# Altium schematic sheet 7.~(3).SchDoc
size 420 x 297 mm
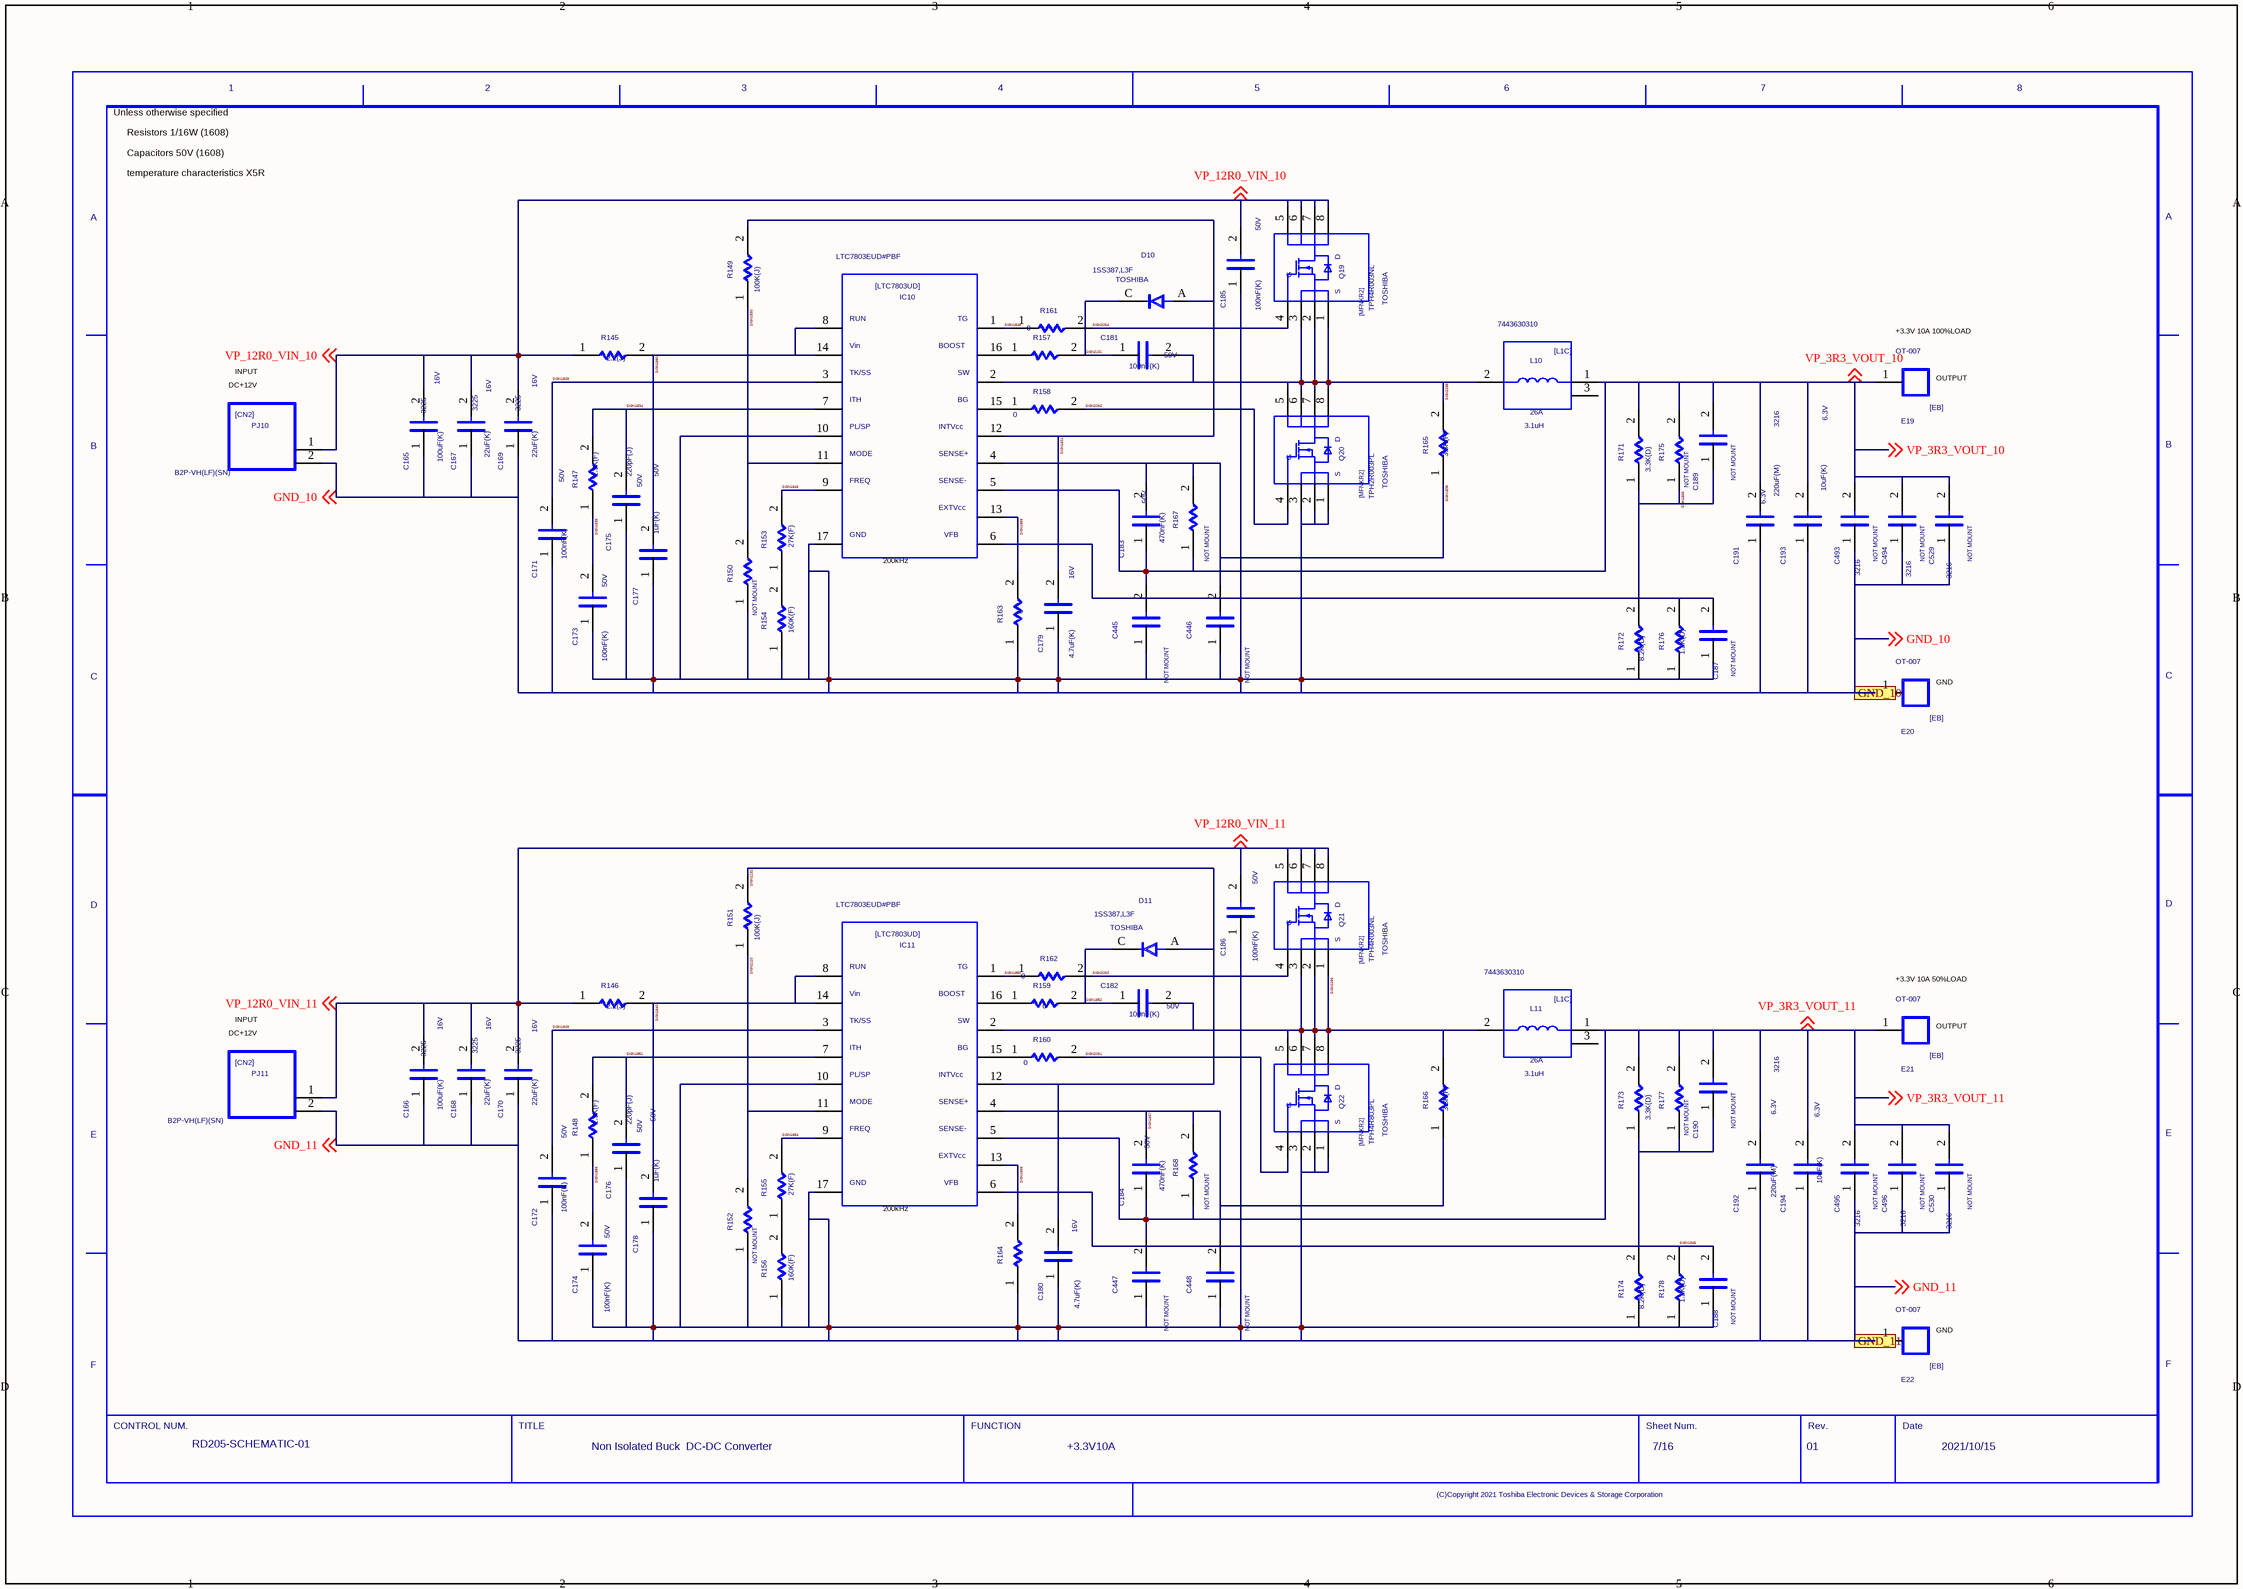
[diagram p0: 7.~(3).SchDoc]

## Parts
C165  SIZECODESMD: 3225  VAL2: 16V  VAL1: 100uF(K)  (hidden comment: C)
C166  SIZECODESMD: 3225  VAL2: 16V  VAL1: 100uF(K)  (hidden comment: C)
C167  SIZECODESMD: 3225  VAL2: 16V  VAL1: 22uF(K)  (hidden comment: C)
C168  SIZECODESMD: 3225  VAL2: 16V  VAL1: 22uF(K)  (hidden comment: C)
C169  SIZECODESMD: 3225  VAL2: 16V  VAL1: 22uF(K)  (hidden comment: C)
C170  SIZECODESMD: 3225  VAL2: 16V  VAL1: 22uF(K)  (hidden comment: C)
C171  VAL2: 50V  VAL1: 100nF(K)  (hidden comment: C)
C172  VAL2: 50V  VAL1: 100nF(K)  (hidden comment: C)
C173  VAL2: 50V  VAL1: 100nF(K)  (hidden comment: C)
C174  VAL2: 50V  VAL1: 100nF(K)  (hidden comment: C)
C175  VAL2: 50V  VAL1: 220pF(J)  (hidden comment: C)
C176  VAL2: 50V  VAL1: 220pF(J)  (hidden comment: C)
C177  VAL2: 50V  VAL1: 1uF(K)  (hidden comment: C)
C178  VAL2: 50V  VAL1: 1uF(K)  (hidden comment: C)
C179  VAL2: 16V  VAL1: 4.7uF(K)  (hidden comment: C)
C180  VAL2: 16V  VAL1: 4.7uF(K)  (hidden comment: C)
C181  VAL2: 50V  VAL1: 100nF(K)  (hidden comment: C)
C182  VAL2: 50V  VAL1: 100nF(K)  (hidden comment: C)
C183  VAL2: 50V  VAL1: 470nF(K)  (hidden comment: C)
C184  VAL2: 50V  VAL1: 470nF(K)  (hidden comment: C)
C185  VAL2: 50V  VAL1: 100nF(K)  (hidden comment: C)
C186  VAL2: 50V  VAL1: 100nF(K)  (hidden comment: C)
C187  NOTMOUNT: NOT MOUNT  (hidden comment: C)
C188  NOTMOUNT: NOT MOUNT  (hidden comment: C)
C189  NOTMOUNT: NOT MOUNT  (hidden comment: C)
C190  NOTMOUNT: NOT MOUNT  (hidden comment: C)
C191  SIZECODESMD: 3216  VAL2: 6.3V  VAL1: 220uF(M)  (hidden comment: C)
C192  SIZECODESMD: 3216  VAL2: 6.3V  VAL1: 220uF(M)  (hidden comment: C)
C193  VAL2: 6.3V  VAL1: 10uF(K)  (hidden comment: C)
C194  VAL2: 6.3V  VAL1: 10uF(K)  (hidden comment: C)
C445  NOTMOUNT: NOT MOUNT  (hidden comment: C)
C446  NOTMOUNT: NOT MOUNT  (hidden comment: C)
C447  NOTMOUNT: NOT MOUNT  (hidden comment: C)
C448  NOTMOUNT: NOT MOUNT  (hidden comment: C)
C493  NOTMOUNT: NOT MOUNT  SIZECODESMD: 3216  (hidden comment: C)
C494  NOTMOUNT: NOT MOUNT  SIZECODESMD: 3216  (hidden comment: C)
C495  NOTMOUNT: NOT MOUNT  SIZECODESMD: 3216  (hidden comment: C)
C496  NOTMOUNT: NOT MOUNT  SIZECODESMD: 3216  (hidden comment: C)
C529  NOTMOUNT: NOT MOUNT  SIZECODESMD: 3216  (hidden comment: C)
C530  NOTMOUNT: NOT MOUNT  SIZECODESMD: 3216  (hidden comment: C)
D10  USERCOMPTEXT3: TOSHIBA  VAL3: 1SS387,L3F  (hidden comment: D)
D11  USERCOMPTEXT3: TOSHIBA  VAL3: 1SS387,L3F  (hidden comment: D)
E19  VAL3: OT-007  (hidden comment: EB)
E20  VAL3: OT-007  (hidden comment: EB)
E21  VAL3: OT-007  (hidden comment: EB)
E22  VAL3: OT-007  (hidden comment: EB)
IC10  VAL3: LTC7803EUD#PBF  (hidden comment: LTC7803UD)
IC11  VAL3: LTC7803EUD#PBF  (hidden comment: LTC7803UD)
L10  VAL3: 7443630310  VAL2: 26A  VAL1: 3.1uH  (hidden comment: L1C)
L11  VAL3: 7443630310  VAL2: 26A  VAL1: 3.1uH  (hidden comment: L1C)
PJ10  VAL3: B2P-VH(LF)(SN)  (hidden comment: CN2)
PJ11  VAL3: B2P-VH(LF)(SN)  (hidden comment: CN2)
Q19  USERCOMPTEXT3: TOSHIBA  VAL3: TPH4R003NL  (hidden comment: MFNKR2)
Q20  USERCOMPTEXT3: TOSHIBA  VAL3: TPH2R003PL  (hidden comment: MFNKR2)
Q21  USERCOMPTEXT3: TOSHIBA  VAL3: TPH4R003NL  (hidden comment: MFNKR2)
Q22  USERCOMPTEXT3: TOSHIBA  VAL3: TPH4R803PL  (hidden comment: MFNKR2)
R145  VAL1: 2.2(J)  (hidden comment: R)
R146  VAL1: 2.2(J)  (hidden comment: R)
R147  VAL1: 1.3K(F)  (hidden comment: R)
R148  VAL1: 1.3K(F)  (hidden comment: R)
R149  VAL1: 100K(J)  (hidden comment: R)
R150  NOTMOUNT: NOT MOUNT  (hidden comment: R)
R151  VAL1: 100K(J)  (hidden comment: R)
R152  NOTMOUNT: NOT MOUNT  (hidden comment: R)
R153  VAL1: 27K(F)  (hidden comment: R)
R154  VAL1: 160K(F)  (hidden comment: R)
R155  VAL1: 27K(F)  (hidden comment: R)
R156  VAL1: 160K(F)  (hidden comment: R)
R157  VAL1: 0  (hidden comment: R)
R158  VAL1: 0  (hidden comment: R)
R159  VAL1: 0  (hidden comment: R)
R160  VAL1: 0  (hidden comment: R)
R161  VAL1: 0  (hidden comment: R)
R162  VAL1: 0  (hidden comment: R)
R163  VAL1: 0  (hidden comment: R)
R164  VAL1: 0  (hidden comment: R)
R165  VAL1: 3.3K(F)  (hidden comment: R)
R166  VAL1: 3.3K(F)  (hidden comment: R)
R167  NOTMOUNT: NOT MOUNT  (hidden comment: R)
R168  NOTMOUNT: NOT MOUNT  (hidden comment: R)
R171  VAL1: 3.3K(D)  (hidden comment: R)
R172  VAL1: 8.2K(D)  (hidden comment: R)
R173  VAL1: 3.3K(D)  (hidden comment: R)
R174  VAL1: 8.2K(D)  (hidden comment: R)
R175  NOTMOUNT: NOT MOUNT  (hidden comment: R)
R176  VAL1: 1.2K(D)  (hidden comment: R)
R177  NOTMOUNT: NOT MOUNT  (hidden comment: R)
R178  VAL1: 1.2K(D)  (hidden comment: R)
U?  DATE: 2021/10/15  SHEETNUMBER: 7/16  TITLE: Non Isolated Buck / DC-DC Converter  REVISION: 01  DRAWINGNUMBER: RD205-SCHEMATIC-01  FUNCTION: +3.3V10A  (hidden comment: WAKU_DEF100)

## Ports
GND_10, GND_11

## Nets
GND_10: C165.1 C167.1 C169.1 C171.1 C173.1 C175.1 C177.1 C179.1 C185.1 C187.1 C191.1 C193.1 C445.1 C446.1 C493.1 C494.1 C529.1 E20.1 IC10.10 IC10.17 PJ10.2 Q20.1 Q20.2 Q20.3 R150.1 R154.1 R163.1 R172.1 R176.1 ; off-sheet GND_10, port GND_10
GND_11: C166.1 C168.1 C170.1 C172.1 C174.1 C176.1 C178.1 C180.1 C186.1 C188.1 C192.1 C194.1 C447.1 C448.1 C495.1 C496.1 C530.1 E22.1 IC11.10 IC11.17 PJ11.2 Q22.1 Q22.2 Q22.3 R152.1 R156.1 R164.1 R174.1 R178.1 ; off-sheet GND_11, port GND_11
SIGN1830: IC10.11 R149.1 R150.2
SIGN1831: C179.2 D10.A IC10.12 R149.2
SIGN1834: C175.2 IC10.7 R147.2
SIGN1835: C173.2 R147.1
SIGN1836: C183.2 C446.2 IC10.4 R165.1 R167.2
SIGN1837: C184.2 C448.2 IC11.4 R166.1 R168.2
SIGN1839: C171.2 IC10.3
SIGN1843: C178.2 IC11.8 IC11.14 R146.2
SIGN1845: C188.2 C190.1 IC11.6 R173.1 R174.2 R177.1 R178.2
SIGN1846: IC10.9 R153.2
SIGN1848: IC10.1 R161.1
SIGN1849: C172.2 IC11.3
SIGN1850: IC11.1 R162.1
SIGN1851: C176.2 IC11.7 R148.2
SIGN1852: C182.1 D11.C R159.2
SIGN1854: IC11.9 R155.2
SIGN1856: C187.2 C189.1 IC10.6 R171.1 R172.2 R175.1 R176.2
SIGN1860: C177.2 IC10.8 IC10.14 R145.2
SIGN1866: C174.2 R148.1
SIGN1868: IC10.13 R163.2
SIGN1869: IC11.13 R164.2
SIGN2120: IC11.11 R151.1 R152.2
SIGN2131: C181.1 D10.C R157.2
SIGN2132: C180.2 D11.A IC11.12 R151.2
SIGN2261: Q22.4 R160.2
SIGN2262: Q20.4 R158.2
SIGN2263: Q21.4 R162.2
SIGN2264: Q19.4 R161.2
SIGN2265: C181.2 IC10.2 L10.2 Q19.1 Q19.2 Q19.3 Q20.5 Q20.6 Q20.7 Q20.8 R165.2
SIGN2266: C182.2 IC11.2 L11.2 Q21.1 Q21.2 Q21.3 Q22.5 Q22.6 Q22.7 Q22.8 R166.2
VP_3R3_VOUT_10: C183.1 C189.2 C191.2 C193.2 C445.2 C493.2 C494.2 C529.2 E19.1 IC10.5 L10.1 R167.1 R171.2 R175.2 ; off-sheet VP_3R3_VOUT_10
VP_3R3_VOUT_11: C184.1 C190.2 C192.2 C194.2 C447.2 C495.2 C496.2 C530.2 E21.1 IC11.5 L11.1 R168.1 R173.2 R177.2 ; off-sheet VP_3R3_VOUT_11
VP_12R0_VIN_10: C165.2 C167.2 C169.2 C185.2 PJ10.1 Q19.5 Q19.6 Q19.7 Q19.8 R145.1 ; off-sheet VP_12R0_VIN_10
VP_12R0_VIN_11: C166.2 C168.2 C170.2 C186.2 PJ11.1 Q21.5 Q21.6 Q21.7 Q21.8 R146.1 ; off-sheet VP_12R0_VIN_11
NetIC10_15: IC10.15 R158.1
NetIC10_16: IC10.16 R157.1
NetIC11_15: IC11.15 R160.1
NetIC11_16: IC11.16 R159.1
NetR153_1: R153.1 R154.2
NetR155_1: R155.1 R156.2

Not connected (* = marked no-connect by the designer): L10 3; L11 3

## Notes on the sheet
- Unless otherwise specified
- Resistors 1/16W (1608)
- Capacitors 50V (1608)
- temperature characteristics X5R
- DC+12V
- INPUT
- (near E19) +3.3V 10A 100%LOAD
- (near E19) OUTPUT
- (near IC10) 200kHz
- (near E20) GND
- (near E21) +3.3V 10A 50%LOAD
- (near E21) OUTPUT
- (near IC11) 200kHz
- (near E22) GND

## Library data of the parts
C165 C166 = C_Dup1: SQ_PART_MODEL: CON_100n; FNPARTSNAMEG: CHIP CERAMIC CAPACITOR (3225); USEINPARTSLIST: YES; OriginalSymbolOrigin: (2540,7620); MFSOLDERINGPROP: .; TEMPCHARACTERI2: B; MFFORMINGDIVP: KC; OUMECLASSIFICATION: セラミックコンデンサ; MFMOUNTSYMBOLP: 90; CDMASTERCADCELG: DC903A; PCODE: P03276001115; FNCLASSCODEG: P03-03; MAXGCOUNT: 1; RATEDVOLTAGE: 250; COMPONENTNAME: G36030160049; OUMEMAKER: KYC 京セラ; MFPACKAGEMETHOP: S; NOMINALCAPACITA: 100n; OUMEMAKERKATAMEI: CF32W5R104K250AT; CAPACITANCETOLE: K
C167-C170 = C_Dup1: SQ_PART_MODEL: CON_22u; FNPARTSNAMEG: CHIP CERAMIC CAPACITOR (3225); USEINPARTSLIST: YES; OriginalSymbolOrigin: (2540,7620); MFSOLDERINGPROP: .; TEMPCHARACTERI2: B; MFFORMINGDIVP: KC; OUMECLASSIFICATION: セラミックコンデンサ; MFMOUNTSYMBOLP: 80; CDMASTERCADCELG: DC903A; PCODE: P03043035626; FNCLASSCODEG: P03-03; MAXGCOUNT: 1; RATEDVOLTAGE: 6.3; COMPONENTNAME: G36030119054; OUMEMAKER: TYD 太陽誘電; MFPACKAGEMETHOP: S; NOMINALCAPACITA: 22u; OUMEMAKERKATAMEI: JMK325BJ226KM-T; CAPACITANCETOLE: K
C171-C174 C181 C182 C185 C186 = C_Dup1: SQ_PART_MODEL: CON_100n; FNPARTSNAMEG: CHIP CERAMIC CAPACITOR (1608); USEINPARTSLIST: YES; OriginalSymbolOrigin: (2540,7620); MFSOLDERINGPROP: .; TEMPCHARACTERI2: B; MFFORMINGDIVP: KC; OUMECLASSIFICATION: セラミックコンデンサ; SIZECODESMD: 1608; MFMOUNTSYMBOLP: 80; CDMASTERCADCELG: C8100E; PCODE: P03B000000E4; FNCLASSCODEG: P03-03; MAXGCOUNT: 1; RATEDVOLTAGE: 16; COMPONENTNAME: GDM030000598; OUMEMAKER: MRT 村田製作所; MFPACKAGEMETHOP: S; NOMINALCAPACITA: 100n; OUMEMAKERKATAMEI: GRM188B11C104KA01C; CAPACITANCETOLE: K
C175 C176 = C_Dup1: SQ_PART_MODEL: CON_220p; FNPARTSNAMEG: CHIP CERAMIC CAPACITOR (1608); USEINPARTSLIST: YES; OriginalSymbolOrigin: (2540,7620); CDMASTERCADCELG: C8100E; MFSOLDERINGPROP: .; TEMPCHARACTERI2: CH; MFFORMINGDIVP: KC; OUMECLASSIFICATION: セラミックコンデンサ; SIZECODESMD: 1608; MFMOUNTSYMBOLP: 80; PCODE: P03039269127; FNCLASSCODEG: P03-03; MAXGCOUNT: 1; RATEDVOLTAGE: 50; COMPONENTNAME: G36030011488; OUMEMAKER: KYC 京セラ; MFPACKAGEMETHOP: S; NOMINALCAPACITA: 220p; OUMEMAKERKATAMEI: CM105CH221J50AT; CAPACITANCETOLE: J
C177 C178 = C_Dup1: SQ_PART_MODEL: CON_1u; FNPARTSNAMEG: CHIP CERAMIC CAPACITOR (1608); USEINPARTSLIST: YES; OriginalSymbolOrigin: (2540,7620); MFSOLDERINGPROP: .; TEMPCHARACTERI2: B; MFFORMINGDIVP: KC; OUMECLASSIFICATION: セラミックコンデンサ; SIZECODESMD: 1608; MFMOUNTSYMBOLP: 80; CDMASTERCADCELG: C8100E; PCODE: P03039ACE122; FNCLASSCODEG: P03-03; MAXGCOUNT: 1; RATEDVOLTAGE: 6.3; COMPONENTNAME: G36030104159; OUMEMAKER: KYC 京セラ; MFPACKAGEMETHOP: S; NOMINALCAPACITA: 1u; OUMEMAKERKATAMEI: CM105B105K06ATN; CAPACITANCETOLE: K
C179 C180 = C_Dup1: SQ_PART_MODEL: CON_4.7u; FNPARTSNAMEG: CHIP CERAMIC CAPACITOR (1608); USEINPARTSLIST: YES; OriginalSymbolOrigin: (2540,7620); MFSOLDERINGPROP: .; TEMPCHARACTERI2: B; MFFORMINGDIVP: KC; OUMECLASSIFICATION: セラミックコンデンサ; SIZECODESMD: 1608; MFMOUNTSYMBOLP: 80; CDMASTERCADCELG: C8100E; PCODE: P03B000000MS; FNCLASSCODEG: P03-03; MAXGCOUNT: 1; RATEDVOLTAGE: 4; COMPONENTNAME: GDM030000053; OUMEMAKER: KYC 京セラ; MFPACKAGEMETHOP: S; NOMINALCAPACITA: 4.7u; OUMEMAKERKATAMEI: CM105B475M04AT; CAPACITANCETOLE: M
C183 C184 = C_Dup1: SQ_PART_MODEL: CON_470n; FNPARTSNAMEG: CHIP CERAMIC CAPACITOR (1608); USEINPARTSLIST: YES; OriginalSymbolOrigin: (2540,7620); MFSOLDERINGPROP: .; TEMPCHARACTERI2: B; MFFORMINGDIVP: KC; OUMECLASSIFICATION: セラミックコンデンサ; SIZECODESMD: 1608; MFMOUNTSYMBOLP: 80; CDMASTERCADCELG: C8100E; PCODE: P03039ABG127; FNCLASSCODEG: P03-03; MAXGCOUNT: 1; RATEDVOLTAGE: 10; COMPONENTNAME: GDM030001129; OUMEMAKER: KYC 京セラ; MFPACKAGEMETHOP: S; NOMINALCAPACITA: 470n; OUMEMAKERKATAMEI: CM105B474K10AT; CAPACITANCETOLE: K
C187-C190 = C_Dup1: SQ_PART_MODEL: CON_100p; FNPARTSNAMEG: CHIP CERAMIC CAPACITOR (1608); USEINPARTSLIST: YES; OriginalSymbolOrigin: (2540,7620); TOLERANCE: J; ASIMVALUE: 100P; MFSOLDERINGPROP: .; TEMPCHARACTERI2: CH; MFFORMINGDIVP: KC; OUMECLASSIFICATION: セラミックコンデンサ; SIZECODESMD: 1608; MFMOUNTSYMBOLP: 80; CDMASTERCADCELG: C8100E; PCODE: P03039177125; FNCLASSCODEG: P03-03; MAXGCOUNT: 1; RATEDVOLTAGE: 50; COMPONENTNAME: G36030011365; OUMEMAKER: KYC 京セラ; MFPACKAGEMETHOP: S; OUMEMAKERKATAMEI: CM105CH101J50AT; VAL2: 50V; VAL1: 100pF(J)
C191 C192 = C_Dup1: SQ_PART_MODEL: CON_22u; FNPARTSNAMEG: CHIP CERAMIC CAPACITOR (3216); USEINPARTSLIST: YES; OriginalSymbolOrigin: (2540,7620); MFSOLDERINGPROP: .; TEMPCHARACTERI2: B; MFFORMINGDIVP: KC; OUMECLASSIFICATION: セラミックコンデンサ; MFMOUNTSYMBOLP: 80; CDMASTERCADCELG: DC901A; PCODE: P03B0000004V; FNCLASSCODEG: P03-03; MAXGCOUNT: 1; RATEDVOLTAGE: 6.3; COMPONENTNAME: GDM030000020; OUMEMAKER: KYC 京セラ; MFPACKAGEMETHOP: S; NOMINALCAPACITA: 22u; OUMEMAKERKATAMEI: CM316B226M06AT; CAPACITANCETOLE: M
C193 C194 = C_Dup1: SQ_PART_MODEL: CON_1u; FNPARTSNAMEG: CHIP CERAMIC CAPACITOR (1608); PARTCOMMENT: 代表セル<KC0008> がフットプリントに登録されていません。; USEINPARTSLIST: YES; OriginalSymbolOrigin: (2540,7620); MFSOLDERINGPROP: .; TEMPCHARACTERI2: B; MFFORMINGDIVP: KC; OUMECLASSIFICATION: セラミックコンデンサ; SIZECODESMD: 1608; MFMOUNTSYMBOLP: 80; CDMASTERCADCELG: KC0008; PCODE: P03B000000ZQ; FNCLASSCODEG: P03-03; MAXGCOUNT: 1; RATEDVOLTAGE: 6.3; COMPONENTNAME: GDM030000202; OUMEMAKER: MRT 村田製作所; MFPACKAGEMETHOP: S; NOMINALCAPACITA: 1u; OUMEMAKERKATAMEI: GRM185B10J105KE21D; CAPACITANCETOLE: K
C445-C448 = C_Dup1: SQ_PART_MODEL: CON_220n; FNPARTSNAMEG: CHIP CERAMIC CAPACITOR (1608); PARTCOMMENT: 代表セル<KC0008> がフットプリントに登録されていません。; USEINPARTSLIST: YES; OriginalSymbolOrigin: (2540,7620); MFSOLDERINGPROP: .; TEMPCHARACTERI2: B; MFFORMINGDIVP: KC; OUMECLASSIFICATION: セラミックコンデンサ; SIZECODESMD: 1608; MFMOUNTSYMBOLP: 80; CDMASTERCADCELG: KC0008; PCODE: P03B000001L3; FNCLASSCODEG: P03-03; MAXGCOUNT: 1; RATEDVOLTAGE: 16; COMPONENTNAME: GDM030001129; OUMEMAKER: MRT 村田製作所; MFPACKAGEMETHOP: S; NOMINALCAPACITA: 220n; OUMEMAKERKATAMEI: GRM188B11C224KA01D; VAL2: 16V; VAL1: 220nF(K); CAPACITANCETOLE: K
C493-C496 C529 C530 = C_Dup1: SQ_PART_MODEL: CON_22u; FNPARTSNAMEG: CHIP CERAMIC CAPACITOR (3216); USEINPARTSLIST: YES; OriginalSymbolOrigin: (2540,7620); MFSOLDERINGPROP: .; TEMPCHARACTERI2: B; MFFORMINGDIVP: KC; OUMECLASSIFICATION: セラミックコンデンサ; MFMOUNTSYMBOLP: 80; CDMASTERCADCELG: DC901A; PCODE: P03B0000004V; FNCLASSCODEG: P03-03; MAXGCOUNT: 1; RATEDVOLTAGE: 6.3; COMPONENTNAME: GDM030000020; OUMEMAKER: KYC 京セラ; MFPACKAGEMETHOP: S; NOMINALCAPACITA: 22u; OUMEMAKERKATAMEI: CM316B226M06AT; VAL2: 6.3V; VAL1: 22uF(M); CAPACITANCETOLE: M
D10 D11 = D_Dup1: FNPARTSNAMEG: DIODE; USEINPARTSLIST: YES; PARTNAME: GDM420000143; SAVEAREA0: -565,-171,12979,8058; SAVECOUNT: 1; OriginalSymbolOrigin: (2540,5080); FORWARDVOLTAGEM: 0; MAXREVERSEVOLTA: 80; COMPONENTNAME: GDM420000143_package; MFSOLDERINGPROP: .; OUMEMAKER: TSB 東芝（ＹＰＳＳ）; QUADMODEL: dummymodel; MFPACKAGEMETHOP: S; MFFORMINGDIVP: MM; MOUNTINGFORMSMD: SMD; OUMECLASSIFICATION: 小信号ダイオード; OUMEMAKERKATAMEI: 1SS387(TPH3,F); CDMASTERCADCELG: D8101D; PCODE: P42B0000008E; FNCLASSCODEG: P42-01
E19-E22 = EB_Dup1: FNPARTSNAMEG: TERMINAL; USEINPARTSLIST: YES; PARTNAME: 5P9L1232P001; OUMEPARTTYPE: TB; OriginalSymbolOrigin: (2540,12700); COMPONENTNAME: 5P9L1232P001_package; MAXGCOUNT: 1; MFSOLDERINGPROP: .; OUMEMAKER: オサダ; QUADMODEL: dummymodel; MFPACKAGEMETHOP: I; MFFORMINGDIVP: OD; OUMECLASSIFICATION: 端子台、端子板; CDMASTERCADCELG: DE0009; KIND: PBS; PCODE: P29045001117; TERMINALSTYLE: SC; FNCLASSCODEG: P29-01
IC10 IC11 = LTC7803UD: USEINPARTSLIST: YES; SAVECOUNT: 29; SAVEAREA0: -53177,0,89020,58420; TIME: 16:14:14; UPDATEUSER: q91866sr; UPDATETIME: 13:15:36; OriginalSymbolOrigin: (5080,55880); MAXGCOUNT: 1; COMPONENTNAME: LTC7803UD_LTC7803UD; OUMEMAKER: ANALOG DEVICES
L10 L11 = L1C_Dup1: USEINPARTSLIST: YES; PARTNAME: 7443630140; SAVECOUNT: 6; SAVEAREA0: -5636,-341,27978,18652; OriginalSymbolOrigin: (5080,15240); COMPONENTNAME: L1C_L1C; MAXGCOUNT: 1; OUMEMAKER: WURTH
PJ10 PJ11 = CN2_Dup1: FNPARTSNAMEG: 3.96PITCH NYLON CONNECTOR; USEINPARTSLIST: YES; PARTNAME: G36220114012; OUMEPARTTYPE: CN; OriginalSymbolOrigin: (2540,15240); MAXGCOUNT: 1; RATEDCURRENT: 7; COMPONENTNAME: G36220114012_package; MFSOLDERINGPROP: .; OUMEMAKER: JST 日本圧着端子製造; NUMBEROFCONTACT: 2; QUADMODEL: dummymodel; MFPACKAGEMETHOP: I; MFFORMINGDIVP: CU; CONTACTPITCH: 3.96m; OUMEMAKERKATAMEI: B2P-VH; CDMASTERCADCELG: DPJ514; PCODE: P22346001114; TERMINALSTYLE: PW; FNCLASSCODEG: P22-10
Q19-Q22 = MFNKR2: USEINPARTSLIST: YES; PARTNAME: TPH6R003NL; SAVEAREA0: -9199,-39,32138,22820; TIME: 18:57:44; UPDATEUSER: q91866sr; UPDATETIME: 12:36:02; SAVECOUNT: 10; OriginalSymbolOrigin: (5080,20320); MAXGCOUNT: 1; COMPONENTNAME: MFNKR2_MFNKR2
R145 R146 = R_Dup1: SQ_PART_MODEL: RES_2.2; FNPARTSNAMEG: CHIP RESISTOR (1608); USEINPARTSLIST: YES; OriginalSymbolOrigin: (5080,5080); TOLERANCE: J; ASIMVALUE: 2.2; MAXGCOUNT: 1; COMPONENTNAME: G36010011507; MFSOLDERINGPROP: .; OUMEMAKER: NAE 松下電子部品; MFPACKAGEMETHOP: S; MFFORMINGDIVP: KC; MOUNTINGFORMSMD: SMD; OUMECLASSIFICATION: 表面実装用固定抵抗器; MFMOUNTSYMBOLP: 80; POWERRATING: 63m; OUMEMAKERKATAMEI: ERJ3GEYJ2R2V; NUMBEROFELEMENT: 0; VAL2: 62.5mW; CDMASTERCADCELG: DR802R; PCODE: P01042157622; FNCLASSCODEG: P01-08
R147 R148 = R_Dup1: SQ_PART_MODEL: RES_1.3K; FNPARTSNAMEG: CHIP RESISTOR (1608); USEINPARTSLIST: YES; OriginalSymbolOrigin: (5080,5080); TOLERANCE: F; ASIMVALUE: 1.3K; MAXGCOUNT: 1; COMPONENTNAME: G36010104049; MFSOLDERINGPROP: .; OUMEMAKER: HDK 北陸電気工業; MFPACKAGEMETHOP: S; MFFORMINGDIVP: KC; MOUNTINGFORMSMD: SMD; OUMECLASSIFICATION: 表面実装用固定抵抗器; MFMOUNTSYMBOLP: 80; POWERRATING: 63m; OUMEMAKERKATAMEI: CR1/16 132FV; NUMBEROFELEMENT: 0; VAL2: 62.5mW; CDMASTERCADCELG: DR802R; PCODE: P01042017223; FNCLASSCODEG: P01-08
R149 R151 = R_Dup1: SQ_PART_MODEL: RES_100K; FNPARTSNAMEG: CHIP RESISTOR (1608); USEINPARTSLIST: YES; OriginalSymbolOrigin: (5080,5080); TOLERANCE: J; ASIMVALUE: 100K; MFSOLDERINGPROP: .; MFPACKAGEMETHOP: S; MFFORMINGDIVP: KC; MOUNTINGFORMSMD: SMD; MFMOUNTSYMBOLP: 80; NUMBEROFELEMENT: 0; PCODE: P01042047220; MAXGCOUNT: 1; COMPONENTNAME: G36010011057; OUMEMAKER: HDK 北陸電気工業; OUMECLASSIFICATION: 表面実装用固定抵抗器; POWERRATING: 63m; OUMEMAKERKATAMEI: CR1/16 104JV; VAL2: 62.5mW; CDMASTERCADCELG: DR802R; FNCLASSCODEG: P01-08
R150 R152 = R_Dup1: SQ_PART_MODEL: RES_10; FNPARTSNAMEG: CHIP RESISTOR (1608); USEINPARTSLIST: YES; OriginalSymbolOrigin: (5080,5080); TOLERANCE: F; ASIMVALUE: 10; MFSOLDERINGPROP: .; MFPACKAGEMETHOP: S; MFFORMINGDIVP: KC; MOUNTINGFORMSMD: SMD; MFMOUNTSYMBOLP: 80; NUMBEROFELEMENT: 0; PCODE: P01042036620; MAXGCOUNT: 1; COMPONENTNAME: G36010104063; OUMEMAKER: NAE 松下電子部品; OUMECLASSIFICATION: 表面実装用固定抵抗器; POWERRATING: 63m; OUMEMAKERKATAMEI: ERJ3GEYF100V; VAL2: 62.5mW; VAL1: 10(F); CDMASTERCADCELG: DR802R; FNCLASSCODEG: P01-08
R153 R155 = R_Dup1: SQ_PART_MODEL: RES_27K; FNPARTSNAMEG: CHIP RESISTOR (1608); USEINPARTSLIST: YES; OriginalSymbolOrigin: (5080,5080); MAXGCOUNT: 1; TOLERANCE: F; COMPONENTNAME: G36010027195; MFSOLDERINGPROP: .; OUMEMAKER: NAE 松下電子部品; MFPACKAGEMETHOP: S; MFFORMINGDIVP: KC; MOUNTINGFORMSMD: SMD; OUMECLASSIFICATION: 表面実装用固定抵抗器; ASIMVALUE: 27K; MFMOUNTSYMBOLP: 80; POWERRATING: 63m; OUMEMAKERKATAMEI: ERJ3GEYF273V; NUMBEROFELEMENT: 0; VAL2: 62.5mW; CDMASTERCADCELG: DR802R; PCODE: P01042508622; FNCLASSCODEG: P01-08
R154 R156 = R_Dup1: SQ_PART_MODEL: RES_160K; FNPARTSNAMEG: CHIP RESISTOR (1608); USEINPARTSLIST: YES; OriginalSymbolOrigin: (5080,5080); MAXGCOUNT: 1; COMPONENTNAME: G51011061108; MFSOLDERINGPROP: .; OUMEMAKER: HDK 北陸電気工業; MFPACKAGEMETHOP: S; MFFORMINGDIVP: KC; MOUNTINGFORMSMD: SMD; OUMECLASSIFICATION: 表面実装用固定抵抗器; RESISTANCETOLER: F; MFMOUNTSYMBOLP: 80; POWERRATING: 63m; OUMEMAKERKATAMEI: CR1/16 164FV; NOMINALRESISTAN: 160K; NUMBEROFELEMENT: 0; VAL2: 62.5mW; CDMASTERCADCELG: DR802R; PCODE: P01042125225; FNCLASSCODEG: P01-08
R157 R159 R163 R164 = R_Dup1: SQ_PART_MODEL: RES_10; FNPARTSNAMEG: CHIP RESISTOR (1608); USEINPARTSLIST: YES; OriginalSymbolOrigin: (5080,5080); TOLERANCE: F; ASIMVALUE: 10; MFSOLDERINGPROP: .; MFPACKAGEMETHOP: S; MFFORMINGDIVP: KC; MOUNTINGFORMSMD: SMD; MFMOUNTSYMBOLP: 80; PCODE: P01042036620; MAXGCOUNT: 1; COMPONENTNAME: G36010104063; OUMEMAKER: NAE 松下電子部品; OUMECLASSIFICATION: 表面実装用固定抵抗器; POWERRATING: 63m; OUMEMAKERKATAMEI: ERJ3GEYF100V; VAL2: 62.5mW; CDMASTERCADCELG: DR802R; FNCLASSCODEG: P01-08
R158 R160-R162 = R_Dup1: SQ_PART_MODEL: RES_10; FNPARTSNAMEG: CHIP RESISTOR (2012); USEINPARTSLIST: YES; OriginalSymbolOrigin: (5080,5080); MAXGCOUNT: 1; TOLERANCE: F; COMPONENTNAME: 5P9L1083P100; MFSOLDERINGPROP: .; OUMEMAKER: 北陸電気工業; MFPACKAGEMETHOP: S; MFFORMINGDIVP: KC; MOUNTINGFORMSMD: SMD; OUMECLASSIFICATION: 表面実装用固定抵抗器; ASIMVALUE: 10; MFMOUNTSYMBOLP: 90; POWERRATING: 100m; OUMEMAKERKATAMEI: CR1/10 100FV Pb(F); VAL2: 125mW; CDMASTERCADCELG: DR910A; PCODE: P01043091222; FNCLASSCODEG: P01-08
R165 R166 = R_Dup1: SQ_PART_MODEL: RES_3.3K; FNPARTSNAMEG: CHIP RESISTOR (1608); USEINPARTSLIST: YES; OriginalSymbolOrigin: (5080,5080); TOLERANCE: F; ASIMVALUE: 3.3K; MAXGCOUNT: 1; COMPONENTNAME: G5101105R107; MFSOLDERINGPROP: .; OUMEMAKER: ROH ロー・; MFPACKAGEMETHOP: S; MFFORMINGDIVP: KC; MOUNTINGFORMSMD: SMD; OUMECLASSIFICATION: 表面実装用固定抵抗器; MFMOUNTSYMBOLP: 80; POWERRATING: 63m; OUMEMAKERKATAMEI: MCR03EZPFX3301; NUMBEROFELEMENT: 0; VAL2: 62.5mW; CDMASTERCADCELG: DR802R; PCODE: P01042250729; FNCLASSCODEG: P01-08
R167 R168 = R_Dup1: SQ_PART_MODEL: RES_68K; FNPARTSNAMEG: CHIP RESISTOR (1608); USEINPARTSLIST: YES; OriginalSymbolOrigin: (5080,5080); TOLERANCE: F; ASIMVALUE: 68K; MAXGCOUNT: 1; COMPONENTNAME: G36010027126; MFSOLDERINGPROP: .; OUMEMAKER: HDK 北陸電気工業; MFPACKAGEMETHOP: S; MFFORMINGDIVP: KC; MOUNTINGFORMSMD: SMD; OUMECLASSIFICATION: 表面実装用固定抵抗器; MFMOUNTSYMBOLP: 80; POWERRATING: 63m; OUMEMAKERKATAMEI: CR1/16 683FV; NUMBEROFELEMENT: 0; VAL2: 62.5mW; VAL1: 68K(F); CDMASTERCADCELG: DR802R; PCODE: P01042456220; FNCLASSCODEG: P01-08
R171 R173 = R_Dup1: SQ_PART_MODEL: RES_3.3K; FNPARTSNAMEG: CHIP RESISTOR (1608); USEINPARTSLIST: YES; OriginalSymbolOrigin: (5080,5080); MAXGCOUNT: 1; COMPONENTNAME: G36010014485; MFSOLDERINGPROP: .; OUMEMAKER: SSM 進工業; MFPACKAGEMETHOP: S; MFFORMINGDIVP: KC; MOUNTINGFORMSMD: SMD; OUMECLASSIFICATION: 表面実装用固定抵抗器; RESISTANCETOLER: D; MFMOUNTSYMBOLP: 80; POWERRATING: 63m; OUMEMAKERKATAMEI: RR0816P-332-D; NOMINALRESISTAN: 3.3K; NUMBEROFELEMENT: 0; VAL2: 62.5mW; CDMASTERCADCELG: DR802R; PCODE: P01042249822; FNCLASSCODEG: P01-08
R172 R174 = R_Dup1: ICX_PART_MODEL: RES_8.2K; FNPARTSNAMEG: CHIP RESISTOR (1608); OriginalSymbolOrigin: (5080,5080); FNCLASSCODEG: P01-08; PCODE: P01117051114; CDMASTERCADCELG: DR802R; USEWITHSCHEMA: YES; VAL2: 62.5mW; NUMBEROFELEMENT: 0; NOMINALRESISTAN: 8.2K; OUMEMAKERKATAMEI: RK73G1JTD822D; POWERRATING: 63m; MFMOUNTSYMBOLP: 80; RESISTANCETOLER: D; FUNCTION: G36010129479; OUMECLASSIFICATION: 表面実装用固定抵抗器; MOUNTINGFORMSMD: SMD; MFFORMINGDIVP: KC; MFPACKAGEMETHOP: S; OUMEMAKER: KOA ＫＯＡ; MFSOLDERINGPROP: .; MAXGCOUNT: 1
R175 R177 = R_Dup1: SQ_PART_MODEL: RES_3.3K; FNPARTSNAMEG: CHIP RESISTOR (1608); USEINPARTSLIST: YES; OriginalSymbolOrigin: (5080,5080); TOLERANCE: F; ASIMVALUE: 3.3K; MAXGCOUNT: 1; COMPONENTNAME: G36010027027; MFSOLDERINGPROP: .; OUMEMAKER: ROH ロー・; MFPACKAGEMETHOP: S; MFFORMINGDIVP: KC; MOUNTINGFORMSMD: SMD; OUMECLASSIFICATION: 表面実装用固定抵抗器; MFMOUNTSYMBOLP: 80; POWERRATING: 63m; OUMEMAKERKATAMEI: MCR03EZPFX3301; NUMBEROFELEMENT: 0; VAL2: 62.5mW; VAL1: 3.3K(F); CDMASTERCADCELG: DR802R; PCODE: P01042250729; FNCLASSCODEG: P01-08
R176 R178 = R_Dup1: ICX_PART_MODEL: RES_1.2K; FNPARTSNAMEG: CHIP RESISTOR (1608); OriginalSymbolOrigin: (5080,5080); FNCLASSCODEG: P01-08; PCODE: P01117031116; CDMASTERCADCELG: DR802R; USEWITHSCHEMA: YES; VAL2: 62.5mW; NUMBEROFELEMENT: 0; NOMINALRESISTAN: 1.2K; OUMEMAKERKATAMEI: RK73G1JTD122D; POWERRATING: 63m; MFMOUNTSYMBOLP: 80; RESISTANCETOLER: D; FUNCTION: G36010129271; OUMECLASSIFICATION: 表面実装用固定抵抗器; MOUNTINGFORMSMD: SMD; MFFORMINGDIVP: KC; MFPACKAGEMETHOP: S; OUMEMAKER: KOA ＫＯＡ; MFSOLDERINGPROP: .; MAXGCOUNT: 1
U? = WAKU_DEF100: PLOTTIME: HH:MM; SAVEAREA0: 330961,54,387907,31546; TIME: 19:23:07; UPDATEUSER: t5459927; UPDATETIME: 15:27:13; SAVECOUNT: 6; OriginalSymbolOrigin: (10160,284480); DESIGNED: ***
